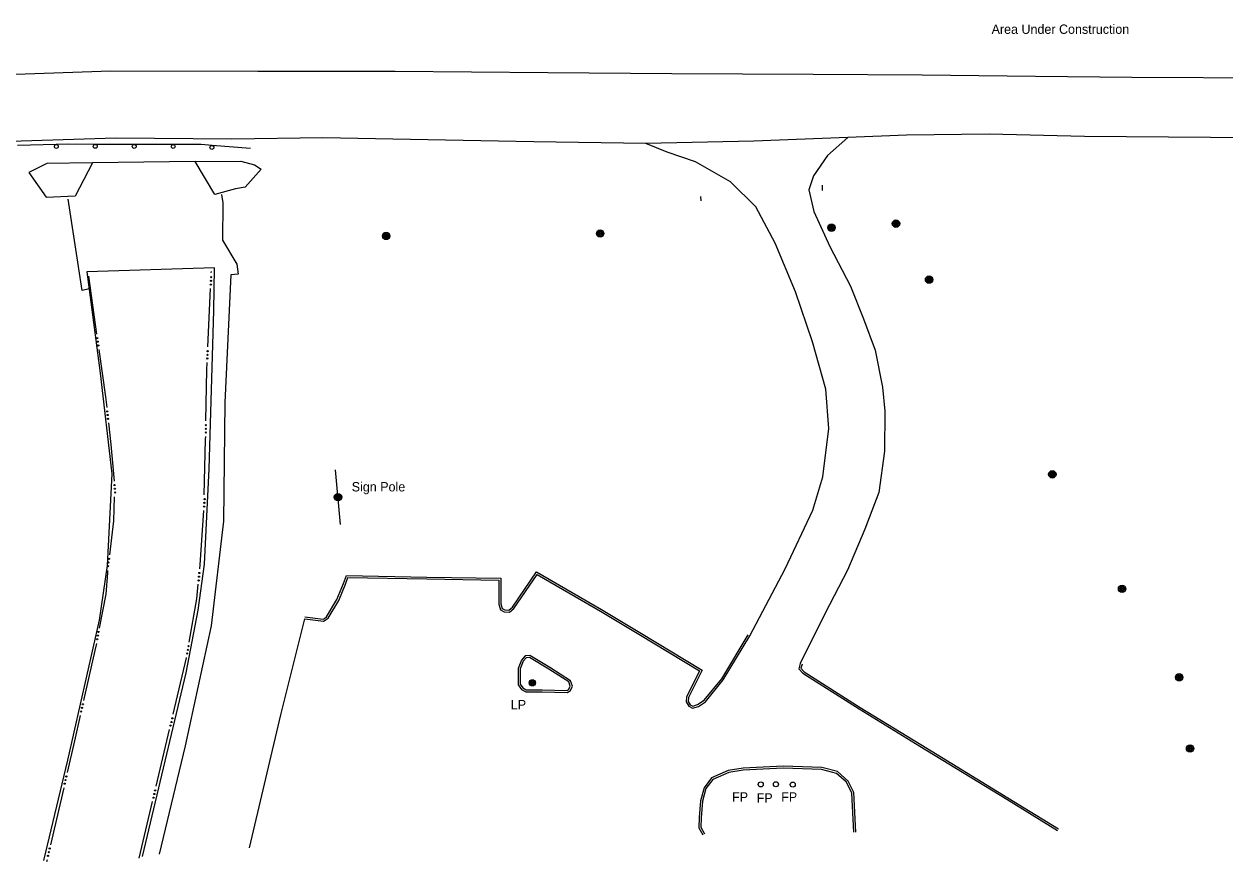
# Model space of a CAD drawing. Extents: x 2402803 to 2427059, y 6985292 to 6997652.
# Drawn here: x 2423250 to 2423867, y 6990852 to 6991282 of the extents above; entities that cross this region are included whole.
import ezdxf

# ---------------------------------------------------------------- set-up
doc = ezdxf.new("R2010")
doc.units = 0
for name, color, linetype in [('p_drainage conc drain', 7, 'Continuous'), ('p_drainage riprap', 7, 'Continuous'), ('p_drainage water', 7, 'Continuous'), ('p_road - paved curb', 7, 'Continuous'), ('p_road bridge end', 7, 'Continuous'), ('p_road guard rails', 7, 'Continuous'), ('p_structure ruins', 7, 'Continuous'), ('p_structure sign', 7, 'Continuous'), ('p_utility manhole', 7, 'Continuous')]:
    doc.layers.add(name, color=color, linetype=linetype)

msp = doc.modelspace()

# ---------------------------------------------------------------- linework, layer by layer
at = {"layer": 'p_drainage conc drain'}
for points in [[(2423351.82, 6991194.31), (2423352.58, 6991190.04), (2423352.3, 6991170.74), (2423359.73, 6991158.56), (2423360.46, 6991153.39), (2423356.67, 6991153.07), (2423353.62, 6991087.49), (2423352.86, 6991026.54), (2423346.54, 6990972.77), (2423333.28, 6990911.17), (2423319.9, 6990855.6)], [(2423283.85, 6991145.89), (2423280.26, 6991144.92), (2423273.11, 6991191.8)], [(2423311.26, 6990854.39), (2423333.74, 6990948.68), (2423339.9, 6990980.87), (2423343.05, 6991004.44), (2423345.53, 6991053.37), (2423347.85, 6991134.61), (2423348.19, 6991156.66), (2423282.71, 6991154.49), (2423289.61, 6991102.53), (2423295.57, 6991050.91), (2423293.24, 6991003.78), (2423289.01, 6990975.79), (2423272.85, 6990903.96), (2423260.42, 6990852.43)]]:
    msp.add_lwpolyline(points, dxfattribs=at)
at = {"layer": 'p_drainage riprap'}
for points in [[(2423285.58, 6991210.51), (2423262.23, 6991210.25), (2423252.86, 6991205.5), (2423261.89, 6991192.88), (2423276.81, 6991193.53)], [(2423338.35, 6991211.15), (2423361.84, 6991211.31), (2423368.84, 6991209.47), (2423372.23, 6991207.21), (2423363.94, 6991198.05), (2423359.12, 6991197.24), (2423348.42, 6991194.27)]]:
    msp.add_lwpolyline(points, dxfattribs=at)
at = {"layer": 'p_drainage water'}
for p, q in [((2423283.5, 6991152.26), (2423287.76, 6991122.56)), ((2423346.63, 6991153.98), (2423346.67, 6991154.71)), ((2423344.82, 6991116.02), (2423346.25, 6991145.99)), ((2423270.86, 6990889.68), (2423264.12, 6990860.45)), ((2423309.52, 6990853.5), (2423316.46, 6990882.69)), ((2423262.33, 6990852.65), (2423262.09, 6990851.62))]:
    msp.add_line(p, q, dxfattribs=at)
for points in [[(2423288.89, 6991114.64), (2423292.36, 6991090.47), (2423292.96, 6991084.92)], [(2423343.86, 6991078.04), (2423344.26, 6991104.25), (2423344.44, 6991108.03)], [(2423293.83, 6991076.97), (2423295.04, 6991065.89), (2423296.76, 6991047.12)], [(2423343.03, 6991040.05), (2423343.72, 6991068.57), (2423343.74, 6991070.04)], [(2423296.77, 6991039.13), (2423296.36, 6991026.71), (2423294.32, 6991009.25)], [(2423340.67, 6991002.13), (2423340.87, 6991004.2), (2423342.78, 6991032.05)], [(2423293.4, 6991001.31), (2423293.26, 6991000.12), (2423292.53, 6990989.17), (2423289.12, 6990971.67)], [(2423335.29, 6990964.53), (2423339.17, 6990986.73), (2423339.89, 6990994.16)], [(2423287.6, 6990963.82), (2423286.88, 6990960.13), (2423281.09, 6990934.53)], [(2423327.07, 6990927.45), (2423333.88, 6990956.44), (2423333.92, 6990956.65)], [(2423279.33, 6990926.73), (2423276.42, 6990913.85), (2423272.65, 6990897.48)], [(2423318.32, 6990890.47), (2423323.86, 6990913.77), (2423325.24, 6990919.66)]]:
    msp.add_lwpolyline(points, dxfattribs=at)
for centre in [(2423346.53, 6991151.82), (2423346.35, 6991147.98), (2423346.44, 6991149.9), (2423288.04, 6991120.58), (2423288.31, 6991118.68), (2423288.59, 6991116.78), (2423344.72, 6991113.86), (2423344.54, 6991110.03), (2423344.63, 6991111.94), (2423293.18, 6991082.94), (2423293.39, 6991081.03), (2423293.6, 6991079.12), (2423343.77, 6991072.04), (2423343.8, 6991073.96), (2423343.83, 6991075.88), (2423296.95, 6991045.13), (2423297.12, 6991043.21), (2423297.3, 6991041.3), (2423342.91, 6991034.05), (2423343.05, 6991035.96), (2423343.18, 6991037.88), (2423293.65, 6991003.45), (2423293.87, 6991005.36), (2423294.09, 6991007.27), (2423340.27, 6990998.06), (2423340.46, 6990999.98), (2423340.09, 6990996.15), (2423288.01, 6990965.94), (2423288.38, 6990967.82), (2423288.74, 6990969.7), (2423334.59, 6990960.52), (2423334.92, 6990962.41), (2423334.26, 6990958.62), (2423279.81, 6990928.83), (2423280.23, 6990930.71), (2423280.65, 6990932.58), (2423326.14, 6990923.47), (2423326.58, 6990925.34), (2423325.7, 6990921.6), (2423271.34, 6990891.79), (2423271.77, 6990893.66), (2423272.2, 6990895.53), (2423317.37, 6990886.5), (2423317.82, 6990888.37), (2423316.93, 6990884.63), (2423262.81, 6990854.76), (2423263.24, 6990856.63), (2423263.67, 6990858.5)]:
    msp.add_circle(centre, 0.3, dxfattribs=at)
at = {"layer": 'p_road - paved curb'}
for points in [[(2422947.6, 6991228.61), (2422990.63, 6991232.66), (2423035.53, 6991237.45), (2423088.04, 6991243.18), (2423141.83, 6991248.63), (2423189.85, 6991252.47), (2423241.37, 6991255.86), (2423294.98, 6991257.65), (2423370.58, 6991257.49), (2423440.96, 6991257.56), (2423519.39, 6991256.91), (2423583.08, 6991256.39), (2423655.59, 6991256.03), (2423711.57, 6991255.63), (2423769.8, 6991255.03), (2423819.23, 6991254.49), (2423892.66, 6991254.22), (2423949.43, 6991253.19), (2424011.2, 6991252.67), (2424055.37, 6991251.98), (2424091.97, 6991251.79)], [(2424092.52, 6991219.97), (2424026.21, 6991221.4), (2423967.56, 6991222.32), (2423917.5, 6991222.69), (2423859.49, 6991223.54), (2423794.83, 6991223.99), (2423745.86, 6991225.15), (2423703.49, 6991224.71), (2423673.38, 6991223.52), (2423625.16, 6991221.62), (2423569.7, 6991220.39), (2423512.16, 6991221.26), (2423466.83, 6991222.06), (2423403.91, 6991223.37), (2423357.11, 6991222.6), (2423297.52, 6991223.13), (2423238.16, 6991221.26), (2423179.01, 6991216.95), (2423125.23, 6991211.26), (2423057.81, 6991203.42), (2422999.29, 6991195.56), (2422970.01, 6991192.39), (2422946.68, 6991191.48)], [(2423623.01, 6990967.77), (2423641.29, 6991002.05), (2423655.48, 6991032.24), (2423660.61, 6991049.28), (2423663.56, 6991074.13), (2423662.06, 6991094.27), (2423655.3, 6991118.67), (2423646.51, 6991144.33), (2423636.01, 6991169.32), (2423626.11, 6991187.89), (2423613.07, 6991200.74), (2423595.16, 6991211.1), (2423580.6, 6991215.91), (2423569.73, 6991220.39)], [(2423673.38, 6991223.52), (2423662.87, 6991214.2), (2423655.74, 6991203.89), (2423653.39, 6991196.6), (2423655.94, 6991185.47), (2423664.13, 6991167.64), (2423674.72, 6991147.14), (2423681.36, 6991130.44), (2423687.39, 6991114.35), (2423691.19, 6991095.32), (2423692.45, 6991083.1), (2423692.2, 6991062.56), (2423689.23, 6991041.36), (2423682.05, 6991022.44), (2423673.22, 6991001.4), (2423661.83, 6990979.26), (2423648.94, 6990953.49)], [(2423394.59, 6990976.47), (2423404.14, 6990975.32), (2423405.14, 6990975.69), (2423406.55, 6990976.72), (2423412.01, 6990985.88), (2423415.45, 6990994.26), (2423416.7, 6990997.7), (2423457.3, 6990996.9), (2423494.2, 6990996.28), (2423494.28, 6990984), (2423495.12, 6990981.05), (2423497, 6990980.07), (2423499.66, 6990979.83), (2423501.91, 6990981.66), (2423513.9, 6990999.15), (2423546.41, 6990980.39), (2423566.1, 6990968.59), (2423597.31, 6990949.75), (2423590.6, 6990936.25), (2423590.35, 6990933.85), (2423591.72, 6990931.59), (2423593.68, 6990930.52), (2423596.68, 6990931.5), (2423600.37, 6990933.86), (2423609.45, 6990945.07), (2423623.01, 6990967.77)], [(2423394.71, 6990977.46), (2423404.02, 6990976.34), (2423404.66, 6990976.58), (2423405.8, 6990977.41), (2423411.11, 6990986.33), (2423414.52, 6990994.62), (2423416, 6990998.71), (2423457.32, 6990997.9), (2423495.19, 6990997.26), (2423495.28, 6990984.14), (2423495.96, 6990981.74), (2423497.29, 6990981.05), (2423499.34, 6990980.86), (2423501.17, 6990982.34), (2423513.6, 6991000.48), (2423546.92, 6990981.25), (2423566.62, 6990969.45), (2423598.62, 6990950.13), (2423591.58, 6990935.97), (2423591.38, 6990934.08), (2423592.44, 6990932.34), (2423593.78, 6990931.6), (2423596.25, 6990932.41), (2423599.69, 6990934.62), (2423608.63, 6990945.64), (2423622.15, 6990968.28)], [(2423366.17, 6990858.85), (2423382.23, 6990927.08), (2423394.59, 6990976.47)], [(2423520.38, 6990951.42), (2423510.13, 6990957.57), (2423507.8, 6990957.44), (2423505.88, 6990955.22), (2423504.1, 6990950.9), (2423504.21, 6990942.6), (2423505.81, 6990940.19), (2423508.01, 6990938.96), (2423516.46, 6990939.04)], [(2423519.87, 6990950.56), (2423509.88, 6990956.55), (2423508.28, 6990956.47), (2423506.74, 6990954.69), (2423505.1, 6990950.71), (2423505.21, 6990942.91), (2423506.51, 6990940.94), (2423508.27, 6990939.96), (2423516.45, 6990940.04)], [(2423648.94, 6990953.49), (2423648.24, 6990950.76), (2423650.34, 6990948.5), (2423679.22, 6990930.15), (2423710.39, 6990911.1), (2423755.05, 6990883.78), (2423781.02, 6990867.84)], [(2423516.46, 6990939.04), (2423529.53, 6990938.6), (2423530.97, 6990939.65), (2423531.97, 6990941.85), (2423531.05, 6990944.67), (2423520.38, 6990951.42)], [(2423516.49, 6990940.04), (2423529.22, 6990939.61), (2423530.17, 6990940.3), (2423530.9, 6990941.91), (2423530.21, 6990944.02), (2423519.85, 6990950.57)], [(2423649.91, 6990953.24), (2423649.34, 6990951.04), (2423650.98, 6990949.27), (2423679.75, 6990931), (2423710.91, 6990911.95), (2423755.57, 6990884.63), (2423781.54, 6990868.69)], [(2423677.52, 6990866.97), (2423676.45, 6990887.24), (2423673.47, 6990893.15), (2423668.05, 6990897.98), (2423660.03, 6990900.07), (2423640.25, 6990900.78), (2423619.61, 6990899.81), (2423611.94, 6990898.54), (2423603.43, 6990894.83), (2423599.61, 6990889.72), (2423597.73, 6990883.03), (2423597.1, 6990874.39), (2423596.91, 6990869.22), (2423599.01, 6990865.54)], [(2423676.52, 6990866.92), (2423675.46, 6990886.98), (2423672.66, 6990892.53), (2423667.56, 6990897.07), (2423659.88, 6990899.07), (2423640.26, 6990899.78), (2423619.72, 6990898.81), (2423612.23, 6990897.57), (2423604.07, 6990894.02), (2423600.52, 6990889.27), (2423598.72, 6990882.86), (2423598.1, 6990874.34), (2423597.92, 6990869.47), (2423599.88, 6990866.04)]]:
    msp.add_lwpolyline(points, dxfattribs=at)
at = {"layer": 'p_road bridge end'}
for points in [[(2423348.42, 6991194.27), (2423338.31, 6991211.21), (2423285.61, 6991210.58), (2423276.75, 6991193.41)], [(2423660.19, 6991199.03), (2423660.24, 6991196.3)], [(2423597.79, 6991193.2), (2423597.94, 6991191.07)]]:
    msp.add_lwpolyline(points, dxfattribs=at)
at = {"layer": 'p_road guard rails'}
for p, q in [((2423267.05, 6991219.88), (2423247.05, 6991219.34)), ((2423307.04, 6991219.94), (2423287.04, 6991220)), ((2423327.04, 6991219.88), (2423307.04, 6991219.94)), ((2423366.82, 6991217.94), (2423346.99, 6991219.42))]:
    msp.add_line(p, q, dxfattribs=at)
for points in [[(2423287.04, 6991220), (2423272.86, 6991220.04), (2423267.05, 6991219.88)], [(2423346.99, 6991219.42), (2423341.35, 6991219.84), (2423327.04, 6991219.88)]]:
    msp.add_lwpolyline(points, dxfattribs=at)
for centre in [(2423267.07, 6991218.88), (2423287.04, 6991219), (2423307.04, 6991218.94), (2423327.04, 6991218.88), (2423346.92, 6991218.42)]:
    msp.add_circle(centre, 1, dxfattribs=at)
at = {"layer": 'p_structure sign'}
msp.add_line((2423412.93, 6991024.87), (2423410.37, 6991052.99), dxfattribs=at)
for radius in [1.9, 1.44, 0.973, 0.539, 0.192]:
    msp.add_circle((2423411.65, 6991038.93), radius, dxfattribs=at)
at = {"layer": 'p_utility manhole'}
for centre, radius in [((2423546.2, 6991174.22), 1.9), ((2423546.2, 6991174.22), 1.44), ((2423665.02, 6991177.19), 1.9), ((2423665.02, 6991177.19), 1.44), ((2423665.02, 6991177.19), 0.973), ((2423665.02, 6991177.19), 0.539), ((2423665.02, 6991177.19), 0.192), ((2423698.11, 6991179.28), 1.9), ((2423698.11, 6991179.28), 1.44), ((2423698.11, 6991179.28), 0.973), ((2423698.11, 6991179.28), 0.539), ((2423698.11, 6991179.28), 0.192), ((2423436.39, 6991172.99), 1.9), ((2423436.39, 6991172.99), 1.44), ((2423436.39, 6991172.99), 0.973), ((2423436.39, 6991172.99), 0.539), ((2423436.39, 6991172.99), 0.192), ((2423546.2, 6991174.22), 0.973), ((2423546.2, 6991174.22), 0.539), ((2423546.2, 6991174.22), 0.192), ((2423715.09, 6991150.56), 1.9), ((2423715.09, 6991150.56), 1.44), ((2423715.09, 6991150.56), 0.973), ((2423715.09, 6991150.56), 0.539), ((2423715.09, 6991150.56), 0.192), ((2423778.36, 6991050.59), 1.9), ((2423778.36, 6991050.59), 1.44), ((2423778.36, 6991050.59), 0.973), ((2423778.36, 6991050.59), 0.539), ((2423778.36, 6991050.59), 0.192), ((2423814.17, 6990991.83), 1.9), ((2423814.17, 6990991.83), 1.44), ((2423814.17, 6990991.83), 0.973), ((2423814.17, 6990991.83), 0.539), ((2423814.17, 6990991.83), 0.192), ((2423843.5, 6990946.43), 1.9), ((2423843.5, 6990946.43), 1.44), ((2423843.5, 6990946.43), 0.973), ((2423511.39, 6990943.59), 1.6), ((2423511.39, 6990943.59), 1.3), ((2423511.39, 6990943.59), 1), ((2423511.39, 6990943.59), 0.539), ((2423511.39, 6990943.59), 0.192), ((2423843.5, 6990946.43), 0.539), ((2423843.5, 6990946.43), 0.192), ((2423849.07, 6990909.88), 1.9), ((2423849.07, 6990909.88), 1.44), ((2423849.07, 6990909.88), 0.973), ((2423849.07, 6990909.88), 0.539), ((2423849.07, 6990909.88), 0.192), ((2423628.68, 6990891.44), 1.3), ((2423636.46, 6990891.5), 1.3), ((2423645.11, 6990891.36), 1.3)]:
    msp.add_circle(centre, radius, dxfattribs=at)

# ---------------------------------------------------------------- texts
at = {"layer": 'p_structure ruins'}
msp.add_text('Area Under Construction', height=4.8, dxfattribs=at).set_placement((2423747.19, 6991276.71))
at = {"layer": 'p_structure sign'}
msp.add_text('Sign Pole', height=4.8, dxfattribs=at).set_placement((2423418.7, 6991041.83))
at = {"layer": 'p_utility manhole'}
for s, p in [('  LP', (2423496.8, 6990930)), ('  FP', (2423610.41, 6990882.58)), ('  FP', (2423623.02, 6990882.07)), ('  FP', (2423635.6, 6990882.6))]:
    msp.add_text(s, height=4.8, dxfattribs=at).set_placement(p)

doc.saveas('drawing.dxf')
